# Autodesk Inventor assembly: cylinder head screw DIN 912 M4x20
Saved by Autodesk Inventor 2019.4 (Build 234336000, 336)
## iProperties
Created: 2021-08
Part Number: cylinder head screw DIN 912 M4x20
Document SubType Name: Assembly
Designer: Administrator
Title: cylinder head screw DIN 912 M4x20 v4
Author: Administrator
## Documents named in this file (2)
- c:\worker\convert-fusion-r06\tmp\job-1\20\output\files\f01db8e3-9ba6-469c-91a4-18b8ab1b818d\cylinder head screw DIN 912 M4x20 v4.iam
- c:\worker\convert-fusion-r06\tmp\job-1\20\output\files\f01db8e3-9ba6-469c-91a4-18b8ab1b818d\HI_WUERTH 00824  20 cylinder head screw DIN 912 M4x20 8.8 BLK.ipt
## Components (1 placed, 1 different names)
1. HI_WUERTH 00824  20 cylinder head screw DIN 912 M4x20 8.8 BLK:1
